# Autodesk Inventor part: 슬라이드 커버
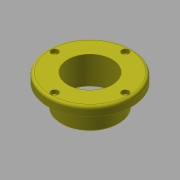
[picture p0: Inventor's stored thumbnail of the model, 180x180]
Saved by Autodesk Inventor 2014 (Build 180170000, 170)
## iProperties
Created: 2015-10
Part Number: 슬라이드 커버
Document SubType Name: Modeling
Designer: mdu
Density: 7.86 g/cm^3
Material: 강철, 연강
Mass: 598.523 g
Surface Area: 229.996 cm^2
Volume: 76.148 cm^3
Appearance: 밝은 황색
Author: mdu
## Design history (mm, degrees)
sketch "스케치1"
  geometry: C1 r 47.5 at (0, 0); C2 r 32.5 at (0, 0); 1 further point
  constraints: 2 centre point, 2 coincident
  dimensions: "d33" = 95 diameter of C1; "d35" = 65 diameter of C2
extrude "돌출1" new body sketch "스케치1" distance "d0" = 10; taper "d1" = 0 deg
extrude "돌출2" join sketch "스케치1" distance "d2" = 25; taper "d3" = 0 deg
hole "구멍1" diameter "d6" = 50; stored, may be unused: countersink angle "d10" = 90 deg, drill point angle "d12" = 118 deg; dims "d4" = 10, "d5" = 10, "d7" = 6, "d8" = 4, "d9" = 2, "d11" = 8
sketch "스케치2" dims "d36" = 80
  geometry: 4 further points
  constraints: 2 coincident, 2 vertical alignment, 2 other
hole "구멍2" sketch "스케치2" at (0, 40) diameter "d13" = 4.5; stored, may be unused: countersink angle "d17" = 90 deg, drill point angle "d19" = 118 deg; dims "d14" = 6, "d15" = 8, "d16" = 4.4, "d18" = 8
fillet "모깎기1" dims "d23" = 3
chamfer "모따기1" distance "d24" = 1; stored, may be unused: second distance "d25" = 2, angle "d26" = 45 deg
sketch "스케치3"
  geometry: C1 r 25 at (0, 0); C2 r 30 at (0, 0); C3 r 26 at (0, 0) reference; 1 further point
  constraints: 2 centre point, 2 coincident
  dimensions: "d27" = 60 diameter of C2
extrude "돌출3" cut sketch "스케치3" distance "d28" = 3; taper "d29" = 0 deg
chamfer "모따기2" distance "d30" = 1; stored, may be unused: second distance "d31" = 2, angle "d32" = 45 deg
node "솔리드1"
pattern_circular "원형 패턴1" dims angle "d21" = 360 deg
